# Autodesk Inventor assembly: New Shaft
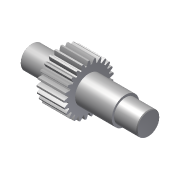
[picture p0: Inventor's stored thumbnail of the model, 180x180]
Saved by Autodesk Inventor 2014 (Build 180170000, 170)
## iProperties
Created: 2011-01
Part Number: New Shaft
Document SubType Name: Assembly
Designer: Beta-8540w
ClientObjectVersion: 1
Author: Beta-8540w
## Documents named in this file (2)
- C:\Inventor 2014 Essentials\Assemblies\Chapter 09\Design Accelerators\Shaft c09-07.iam
- C:\Inventor 2014 Essentials\Assemblies\Chapter 09\Design Accelerators\Shaft c09-05.ipt
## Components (1 placed, 1 different names)
1. New Shaft:1
